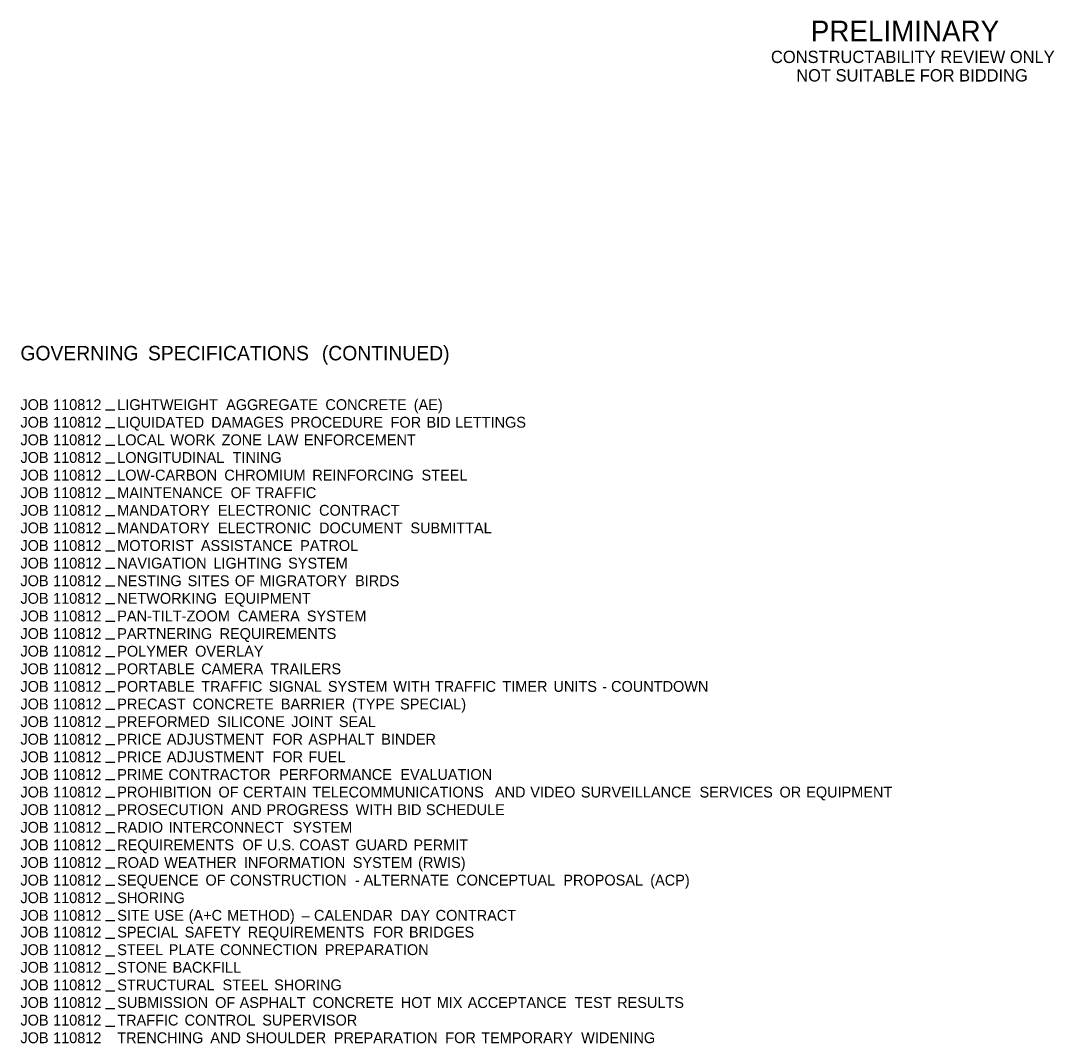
# Model space of a CAD drawing. Extents: x 200 to 2094, y 35 to 1167.
# Drawn here: x 768 to 1340, y 601 to 1167 of the extents above; entities that cross this region are included whole.
import ezdxf

# ---------------------------------------------------------------- set-up
doc = ezdxf.new("R2010")
doc.units = 0
doc.layers.add('Default', color=7, linetype='Continuous')
doc.layers.add('R_Draft', color=7, linetype='Continuous')

msp = doc.modelspace()

# ---------------------------------------------------------------- linework, layer by layer
at = {"layer": 'Default'}
for p, q in [((820.04, 951.08), (814.8, 951.08)), ((820.04, 941.33), (814.8, 941.33)), ((820.04, 931.58), (814.8, 931.58)), ((820.04, 921.83), (814.8, 921.83)), ((820.04, 912.08), (814.8, 912.08)), ((820.04, 902.33), (814.8, 902.33)), ((820.04, 892.58), (814.8, 892.58)), ((820.04, 882.83), (814.8, 882.83)), ((820.04, 873.08), (814.8, 873.08)), ((820.04, 863.33), (814.8, 863.33)), ((820.04, 853.58), (814.8, 853.58)), ((820.04, 843.83), (814.8, 843.83)), ((820.04, 834.08), (814.8, 834.08)), ((820.04, 824.33), (814.8, 824.33)), ((820.04, 814.58), (814.8, 814.58)), ((820.04, 804.83), (814.8, 804.83)), ((820.04, 795.08), (814.8, 795.08)), ((820.04, 785.33), (814.8, 785.33)), ((820.04, 775.58), (814.8, 775.58)), ((820.04, 765.83), (814.8, 765.83)), ((820.04, 756.08), (814.8, 756.08)), ((820.04, 746.33), (814.8, 746.33)), ((820.04, 736.58), (814.8, 736.58)), ((820.04, 726.83), (814.8, 726.83)), ((820.04, 717.08), (814.8, 717.08)), ((820.04, 707.33), (814.8, 707.33)), ((820.04, 697.58), (814.8, 697.58)), ((820.04, 687.83), (814.8, 687.83)), ((820.04, 678.08), (814.8, 678.08)), ((820.04, 668.33), (814.8, 668.33)), ((820.04, 658.58), (814.8, 658.58)), ((820.04, 648.83), (814.8, 648.83)), ((820.04, 639.08), (814.8, 639.08)), ((820.04, 629.33), (814.8, 629.33)), ((820.04, 619.58), (814.8, 619.58)), ((820.04, 609.83), (814.8, 609.83))]:
    msp.add_line(p, q, dxfattribs=at)

# ---------------------------------------------------------------- texts
for s, height, p in [('GOVERNING', 8, (767.74, 978.66)), (' SPECIFICATIONS', 8, (835.39, 978.66)), (' (CONTINUED)', 8, (931.73, 978.66)), ('JOB', 6, (767.74, 951.14)), (' 110812', 6, (783.6, 951.14)), ('LIGHTWEIGHT', 6, (821.37, 951.14)), (' AGGREGATE', 6, (879.42, 951.14)), (' CONCRETE', 6, (934.41, 951.14)), (' (AE)', 6, (983.34, 951.14)), ('JOB', 6, (767.74, 941.39)), (' 110812', 6, (783.6, 941.39)), ('LIQUIDATED', 6, (821.37, 941.39)), (' DAMAGES', 6, (871.23, 941.39)), (' PROCEDURE', 6, (915.05, 941.39)), (' FOR', 6, (970.51, 941.39)), (' BID', 6, (990.42, 941.39)), (' LETTINGS', 6, (1006.27, 941.39)), ('JOB', 6, (767.74, 931.64)), (' 110812', 6, (783.6, 931.64)), ('LOCAL', 6, (821.37, 931.64)), (' WORK', 6, (848.56, 931.64)), (' ZONE', 6, (876.95, 931.64)), (' LAW', 6, (902.12, 931.64)), (' ENFORCEMENT', 6, (922.52, 931.64)), ('JOB', 6, (767.74, 921.89)), (' 110812', 6, (783.6, 921.89)), ('LONGITUDINAL', 6, (821.37, 921.89)), (' TINING', 6, (883.03, 921.89)), ('JOB', 6, (767.74, 912.14)), (' 110812', 6, (783.6, 912.14)), ('LOW-CARBON', 6, (821.37, 912.14)), (' CHROMIUM', 6, (878.44, 912.14)), (' REINFORCING', 6, (927.17, 912.14)), (' STEEL', 6, (987.66, 912.14)), ('JOB', 6, (767.74, 902.39)), (' 110812', 6, (783.6, 902.39)), ('MAINTENANCE', 6, (821.37, 902.39)), (' OF', 6, (881.95, 902.39)), (' TRAFFIC', 6, (895.53, 902.39)), ('JOB', 6, (767.74, 892.64)), (' 110812', 6, (783.6, 892.64)), ('MANDATORY', 6, (821.37, 892.64)), (' ELECTRONIC', 6, (874.88, 892.64)), (' CONTRACT', 6, (930.91, 892.64)), ('JOB', 6, (767.74, 882.89)), (' 110812', 6, (783.6, 882.89)), ('MANDATORY', 6, (821.37, 882.89)), (' ELECTRONIC', 6, (874.88, 882.89)), (' DOCUMENT', 6, (930.91, 882.89)), (' SUBMITTAL', 6, (981.5, 882.89)), ('JOB', 6, (767.74, 873.14)), (' 110812', 6, (783.6, 873.14)), ('MOTORIST', 6, (821.37, 873.14)), (' ASSISTANCE', 6, (865.45, 873.14)), (' PATROL', 6, (920.44, 873.14)), ('JOB', 6, (767.74, 863.39)), (' 110812', 6, (783.6, 863.39)), ('NAVIGATION', 6, (821.37, 863.39)), (' LIGHTING', 6, (872.39, 863.39)), (' SYSTEM', 6, (913.78, 863.39)), ('JOB', 6, (767.74, 853.64)), (' 110812', 6, (783.6, 853.64)), ('NESTING', 6, (821.37, 853.64)), (' SITES', 6, (858.11, 853.64)), (' OF', 6, (884.23, 853.64)), (' MIGRATORY', 6, (897.82, 853.64)), (' BIRDS', 6, (950.85, 853.64)), ('JOB', 6, (767.74, 843.89)), (' 110812', 6, (783.6, 843.89)), ('NETWORKING', 6, (821.37, 843.89)), (' EQUIPMENT', 6, (878.6, 843.89)), ('JOB', 6, (767.74, 834.14)), (' 110812', 6, (783.6, 834.14)), ('PAN-TILT-ZOOM', 6, (821.37, 834.14)), (' CAMERA', 6, (885.94, 834.14)), (' SYSTEM', 6, (924.15, 834.14)), ('JOB', 6, (767.74, 824.39)), (' 110812', 6, (783.6, 824.39)), ('PARTNERING', 6, (821.37, 824.39)), (' REQUIREMENTS', 6, (875.81, 824.39)), ('JOB', 6, (767.74, 814.64)), (' 110812', 6, (783.6, 814.64)), ('POLYMER', 6, (821.37, 814.64)), (' OVERLAY', 6, (862.25, 814.64)), ('JOB', 6, (767.74, 804.89)), (' 110812', 6, (783.6, 804.89)), ('PORTABLE', 6, (821.37, 804.89)), (' CAMERA', 6, (865.65, 804.89)), (' TRAILERS', 6, (903.87, 804.89)), ('JOB', 6, (767.74, 795.14)), (' 110812', 6, (783.6, 795.14)), ('PORTABLE', 6, (821.37, 795.14)), (' TRAFFIC', 6, (865.65, 795.14)), (' SIGNAL', 6, (903.04, 795.14)), (' SYSTEM', 6, (935.82, 795.14)), (' WITH', 6, (972, 795.14)), (' TRAFFIC', 6, (995.06, 795.14)), (' TIMER', 6, (1032.45, 795.14)), (' UNITS', 6, (1060.75, 795.14)), (' -', 6, (1087.79, 795.14)), (' COUNTDOWN', 6, (1092.65, 795.14)), ('JOB', 6, (767.74, 785.39)), (' 110812', 6, (783.6, 785.39)), ('PRECAST', 6, (821.37, 785.39)), (' CONCRETE', 6, (860.8, 785.39)), (' BARRIER', 6, (909.73, 785.39)), (' (TYPE', 6, (949.22, 785.39)), (' SPECIAL)', 6, (975.79, 785.39)), ('JOB', 6, (767.74, 775.64)), (' 110812', 6, (783.6, 775.64)), ('PREFORMED', 6, (821.37, 775.64)), (' SILICONE', 6, (874.49, 775.64)), (' JOINT', 6, (915.5, 775.64)), (' SEAL', 6, (941.88, 775.64)), ('JOB', 6, (767.74, 765.89)), (' 110812', 6, (783.6, 765.89)), ('PRICE', 6, (821.37, 765.89)), (' ADJUSTMENT', 6, (846.55, 765.89)), (' FOR', 6, (905.07, 765.89)), (' ASPHALT', 6, (924.98, 765.89)), (' BINDER', 6, (965.35, 765.89)), ('JOB', 6, (767.74, 756.14)), (' 110812', 6, (783.6, 756.14)), ('PRICE', 6, (821.37, 756.14)), (' ADJUSTMENT', 6, (846.55, 756.14)), (' FOR', 6, (905.07, 756.14)), (' FUEL', 6, (924.98, 756.14)), ('JOB', 6, (767.74, 746.39)), (' 110812', 6, (783.6, 746.39)), ('PRIME', 6, (821.37, 746.39)), (' CONTRACTOR', 6, (847.47, 746.39)), (' PERFORMANCE', 6, (908.84, 746.39)), (' EVALUATION', 6, (975.94, 746.39)), ('JOB', 6, (767.74, 736.64)), (' 110812', 6, (783.6, 736.64)), ('PROHIBITION', 6, (821.37, 736.64)), (' OF', 6, (875.18, 736.64)), (' CERTAIN', 6, (888.77, 736.64)), (' TELECOMMUNICATIONS', 6, (927.21, 736.64)), (' AND', 6, (1028.32, 736.64)), (' VIDEO', 6, (1047.9, 736.64)), (' SURVEILLANCE', 6, (1075.94, 736.64)), (' SERVICES', 6, (1141.65, 736.64)), (' OR', 6, (1185.94, 736.64)), (' EQUIPMENT', 6, (1200.73, 736.64)), ('JOB', 6, (767.74, 726.89)), (' 110812', 6, (783.6, 726.89)), ('PROSECUTION', 6, (821.37, 726.89)), (' AND', 6, (882.17, 726.89)), (' PROGRESS', 6, (901.76, 726.89)), (' WITH', 6, (951.17, 726.89)), (' BID', 6, (974.24, 726.89)), (' SCHEDULE', 6, (990.09, 726.89)), ('JOB', 6, (767.74, 717.14)), (' 110812', 6, (783.6, 717.14)), ('RADIO', 6, (821.37, 717.14)), (' INTERCONNECT', 6, (847.55, 717.14)), (' SYSTEM', 6, (916.31, 717.14)), ('JOB', 6, (767.74, 707.39)), (' 110812', 6, (783.6, 707.39)), ('REQUIREMENTS', 6, (821.37, 707.39)), (' OF', 6, (888.48, 707.39)), (' U.S.', 6, (902.06, 707.39)), (' COAST', 6, (919.96, 707.39)), (' GUARD', 6, (951.01, 707.39)), (' PERMIT', 6, (983.16, 707.39)), ('JOB', 6, (767.74, 697.64)), (' 110812', 6, (783.6, 697.64)), ('ROAD', 6, (821.37, 697.64)), (' WEATHER', 6, (845.15, 697.64)), (' INFORMATION', 6, (889.28, 697.64)), (' SYSTEM', 6, (949.61, 697.64)), (' (RWIS)', 6, (985.78, 697.64)), ('JOB', 6, (767.74, 687.89)), (' 110812', 6, (783.6, 687.89)), ('SEQUENCE', 6, (821.37, 687.89)), (' OF', 6, (867.98, 687.89)), (' CONSTRUCTION', 6, (881.57, 687.89)), (' ALTERNATE', 6, (955.6, 687.89)), (' CONCEPTUAL', 6, (1006.87, 687.89)), (' PROPOSAL', 6, (1066.2, 687.89)), (' (ACP)', 6, (1114.36, 687.89)), (' -', 6, (950.74, 687.89)), ('JOB', 6, (767.74, 678.14)), (' 110812', 6, (783.6, 678.14)), ('SHORING', 6, (821.37, 678.14)), ('JOB', 6, (767.74, 668.39)), (' 110812', 6, (783.6, 668.39)), ('SITE', 6, (821.37, 668.39)), (' USE', 6, (839.56, 668.39)), (' (A+C', 6, (858.68, 668.39)), (' METHOD)', 6, (880, 668.39)), ('–', 6, (923.48, 668.39)), (' CALENDAR', 6, (928.12, 668.39)), (' DAY', 6, (975.99, 668.39)), (' CONTRACT', 6, (995.49, 668.39)), ('JOB', 6, (767.74, 659.12)), (' 110812', 6, (783.6, 659.12)), ('SPECIAL', 6, (821.37, 659.12)), (' SAFETY', 6, (856.49, 659.12)), (' REQUIREMENTS', 6, (891.37, 659.12)), (' FOR', 6, (960.8, 659.12)), (' BRIDGES', 6, (980.71, 659.12)), ('JOB', 6, (767.74, 649.37)), (' 110812', 6, (783.6, 649.37)), ('STEEL', 6, (821.37, 649.37)), (' PLATE', 6, (847.63, 649.37)), (' CONNECTION', 6, (876.07, 649.37)), (' PREPARATION', 6, (934.08, 649.37)), ('JOB', 6, (767.74, 639.62)), (' 110812', 6, (783.6, 639.62)), ('STONE', 6, (821.37, 639.62)), (' BACKFILL', 6, (849.81, 639.62)), ('JOB', 6, (767.74, 629.87)), (' 110812', 6, (783.6, 629.87)), ('STRUCTURAL', 6, (821.37, 629.87)), (' STEEL', 6, (877.44, 629.87)), (' SHORING', 6, (906.03, 629.87)), ('JOB', 6, (767.74, 620.12)), (' 110812', 6, (783.6, 620.12)), ('SUBMISSION', 6, (821.37, 620.12)), (' OF', 6, (873.33, 620.12)), (' ASPHALT', 6, (886.91, 620.12)), (' CONCRETE', 6, (927.28, 620.12)), (' HOT', 6, (976.21, 620.12)), (' MIX', 6, (996.07, 620.12)), (' ACCEPTANCE', 6, (1013.24, 620.12)), (' TEST', 6, (1072.43, 620.12)), (' RESULTS', 6, (1096.02, 620.12)), ('JOB', 6, (767.74, 610.37)), (' 110812', 6, (783.6, 610.37)), ('TRAFFIC', 6, (821.37, 610.37)), (' CONTROL', 6, (856.43, 610.37)), (' SUPERVISOR', 6, (899.45, 610.37)), ('JOB', 6, (767.74, 600.62)), (' 110812', 6, (783.6, 600.62)), ('TRENCHING', 6, (821.37, 600.62)), (' AND', 6, (870.68, 600.62)), (' SHOULDER', 6, (890.26, 600.62)), (' PREPARATION', 6, (939.07, 600.62)), (' FOR', 6, (1000.81, 600.62)), (' TEMPORARY', 6, (1020.72, 600.62)), (' WIDENING', 6, (1076.09, 600.62))]:
    msp.add_text(s, height=height, dxfattribs=at).set_placement(p)
at = {"layer": 'R_Draft'}
for s, height, p in [('PRELIMINARY', 11.508, (1205.51, 1155.22)), ('CONSTRUCTABILITY REVIEW ONLY', 6.823, (1183.44, 1143.28)), ('NOT SUITABLE FOR BIDDING', 6.823, (1197.43, 1133.05))]:
    msp.add_text(s, height=height, rotation=0, dxfattribs=at).set_placement(p)

doc.saveas('drawing.dxf')
